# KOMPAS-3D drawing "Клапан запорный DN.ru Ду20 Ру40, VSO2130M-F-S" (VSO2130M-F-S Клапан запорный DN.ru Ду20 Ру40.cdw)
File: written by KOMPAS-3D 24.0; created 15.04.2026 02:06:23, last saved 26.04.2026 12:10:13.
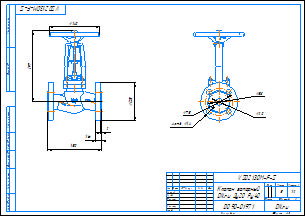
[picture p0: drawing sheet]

Document properties: Автор: DN.ru; Форматы листов документа: A3; Полное имя файла: VSO2130M-F-S Клапан запорный DN.ru Ду20 Ру40.m3d; Масса: 5; Наименование: Клапан запорный DN.ru Ду20 Ру40; Количество листов документа: 1; Примечание: D090-01971

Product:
- Body: Тело 1  | qty 1
    Масса: 5.217639
- Part/product: Клапан запорный DN.ru Ду20 Ру40  | designation VSO2130M-F-S
    Масса: 5
    Раздел спецификации: Прочие изделия
    Примечание: D090-01971

Views: Проекционный вид 2, Вид:1
Referenced files in C:\Работа\VSO2130M-F-S Клапан запорный DN.ru\DN20\: VSO2130M-F-S DN20 PN40  Клапан запорный сильфонный DN.ru.m3d, VSO2130M-F-S Клапан запорный DN.ru Ду20 Ру40.m3d
Referenced files in C:\Program Files\ASCON\KOMPAS-3D v24\Templates\: Чертеж_DN.ru.cdt
Referenced files in C:\Работа\ГОТОВЫЕ ИСХОДНИКИ\VSO2130M-F-S Клапан запорный сильфонный DN.ru Ду15-100 Ру40\DN20\: VSO2130M-F-S Клапан запорный DN.ru Ду20 Ру40.m3d
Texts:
  VSO2130M-F-S
  Чертеж_DN.ru.cdt
  Клапан запорный
  DN.ru Ду20 Ру40
  Клапан запорный DN.ru Ду20 Ру40
  VSO2130M-F-S  Клапан запорный DN.ru Ду20 Ру40
Dimensions and other numbers on the sheet: 0; 3; 5; 4; 20; 58; 75; 4 отв.; 14; 1:2; 1; 2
